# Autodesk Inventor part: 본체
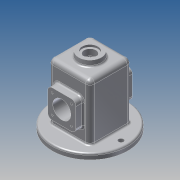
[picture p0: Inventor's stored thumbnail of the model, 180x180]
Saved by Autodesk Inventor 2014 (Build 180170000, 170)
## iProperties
Created: 2021-08
Part Number: 본체
Material: 알루미늄 6061
Document SubType Name: Modeling
Designer: kb542-02
Mass: 821.659 g
Surface Area: 959.349 cm^2
Volume: 303.195 cm^3
Density: 2.71 g/cm^3
Appearance: 알루미늄 - 평지
Author: kb542-02
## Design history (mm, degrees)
sketch "스케치1"
  geometry: L1 (37, 37)-(-37, 37); L2 (-37, 37)-(-37, -37); L3 (-37, -37)-(37, -37); L4 (37, -37)-(37, 37); L5 (37, 37)-(-37, -37); L6 (-37, 37)-(37, -37); 1 further point
  constraints: 12 end point, 2 midpoint, 2 parallel, 1 horizontal, 1 perpendicular
  dimensions: "d0" = 74 distance between parallel lines of L3 L1; "d1" = 74 distance between parallel lines of L4 L2
extrude "돌출1" new body sketch "스케치1" distance "d2" = 110; taper "d3" = 0 deg
sketch "스케치2"
  geometry: L1 (32, 32)-(-32, 32); L2 (-32, 32)-(-32, -32); L3 (-32, -32)-(32, -32); L4 (32, -32)-(32, 32); L5 (32, 32)-(-32, -32); L6 (-32, 32)-(32, -32); 1 further point
  constraints: 12 end point, 2 midpoint, 2 parallel, 1 horizontal, 1 perpendicular
  dimensions: "d4" = 64 distance of L2.end L3.end; "d5" = 64 distance between parallel lines of L3 L1
extrude "돌출2" cut sketch "스케치2" distance "d6" = 105; taper "d7" = 0 deg
sketch "스케치3"
  geometry: L1 (55, 43.476)-(55, -45.763); L2 (0, -32)-(0, 32) reference; L3 (39, 32)-(39, 25); L4 (39, 25)-(32.548, 25); L5 (32.548, 25)-(30, 32); L6 (0, 32)-(105, 32) reference; 1 further point
  constraints: 8 end point, 2 point on line, 1 parallel, 1 perpendicular, 1 vertical
  dimensions: "d8" = 55 distance from line of L2 L1.end; "d11" = 50 diameter of L5.end L1; "d12" = 32 diameter of L3 L1; "d13" = 110 deg angle of L6 L5; "d14" = 7 distance between parallel lines of L6 L4
revolve "회전1" sketch "스케치3" stored, may be unused: angle "d15" = 90 deg
sketch "스케치4"
  geometry: L1 (0, 0)-(0, 110) reference; C1 r 16 at (37, 55); 1 further point
  constraints: 1 centre point
  dimensions: "d16" = 55 distance of point (37, 0) C1.centre; "d17" = 32 diameter of C1; "d18" = 37 distance from line of L1 C1.centre
extrude "돌출3" cut sketch "스케치4" distance "d19" = 105; taper "d20" = 0 deg
sketch "스케치5"
  geometry: L1 (12, 30)-(62, 30); L2 (62, 30)-(62, 80); L3 (62, 80)-(12, 80); L4 (12, 80)-(12, 30); L5 (12, 30)-(62, 80); L6 (62, 30)-(12, 80); C1 r 16 at (37, 55) reference; 1 further point
  constraints: 12 end point, 2 midpoint, 2 parallel, 1 horizontal, 1 perpendicular
  dimensions: "d21" = 50 distance of L2.end L3.end; "d22" = 50 distance between parallel lines of L3 L1
extrude "돌출4" join sketch "스케치5" distance "d23" = 13; taper "d24" = 0 deg
sketch "스케치6"
  geometry: L1 (-37, 37)-(-37, -37) reference; L2 (37, 37)-(-37, 37) reference; L3 (37, -37)-(37, 37) reference; L4 (-37, -37)-(37, -37) reference; C1 r 67 at (0, 0); 1 further point
  constraints: 1 centre point, 1 coincident
  dimensions: "d25" = 134 diameter of C1
extrude "돌출5" join sketch "스케치6" distance "d26" = 10; taper "d27" = 0 deg
sketch "스케치7"
  geometry: L1 (120, 0)-(120, -20); L2 (120, -20)-(105, -21.577); L3 (0, 0)-(146.518, 0); L4 (105, -32)-(105, 32) reference; L5 (105, -21.577)-(137.115, -21.577); L6 (0, -32)-(0, 32) reference; L7 (105, -21.577)-(105, 0); L8 (120, 0)-(105, 0)
  constraints: 12 end point, 2 perpendicular, 2 point on line, 1 collinear, 1 horizontal, 1 midpoint
  dimensions: "d28" = 6 deg angle of L2 L5; "d29" = 40 diameter of L1.end L3; "d30" = 120 distance between parallel lines of L6 L1
revolve "회전2" sketch "스케치7" stored, may be unused: angle "d31" = 90 deg
sketch "스케치8"
  geometry: C1 r 20 at (0, 0) reference; 1 further point
  constraints: 1 coincident
hole "구멍1" sketch "스케치8" at (0, 0) diameter "d32" = 21; stored, may be unused: countersink angle "d36" = 90 deg, drill point angle "d38" = 0 deg; dims "d33" = 6, "d34" = 28, "d35" = 4, "d37" = 8
sketch "스케치9" dims "d39" = 110
  geometry: C1 r 67 at (0, 0) reference; C2 r 4.5 at (-55, 0); 1 further point
  constraints: 2 horizontal alignment, 1 centre point, 1 coincident, 2 other
  dimensions: "d40" = 9 diameter of C2
extrude "돌출6" cut sketch "스케치9" distance "d41" = 10; taper "d42" = 0 deg
sketch "스케치10" dims "d19" = 105, "d20" = 0
  geometry: L1 (20, 38)-(54, 38); L2 (54, 38)-(54, 72); L3 (54, 72)-(20, 72); L4 (20, 72)-(20, 38); L5 (20, 38)-(54, 72); L6 (54, 38)-(20, 72); C1 r 16 at (37, 55) reference; 5 further points
  constraints: 12 end point, 4 coincident, 2 midpoint, 2 parallel, 1 horizontal, 1 perpendicular
  dimensions: "d43" = 34 distance of L2.end L3.end; "d44" = 34 distance between parallel lines of L3 L1
hole "구멍2" sketch "스케치10" at (54, 72), (20, 72), (20, 38), (54, 38) diameter "d45" = 3.242; stored, may be unused: countersink angle "d49" = 90 deg, drill point angle "d51" = 118 deg; dims "d46" = 8, "d47" = 28, "d48" = 4, "d50" = 10
fillet "모깎기1" dims "d52" = 8
fillet "모깎기2" dims "d53" = 8
fillet "모깎기3" dims "d54" = 3
fillet "모깎기4" dims "d55" = 8
fillet "모깎기5" dims "d56" = 3
fillet "모깎기6" dims "d57" = 8
fillet "모깎기7" dims "d58" = 3
fillet "모깎기8" dims "d59" = 3
fillet "모깎기9" dims "d60" = 3
sketch "스케치11"
  geometry: L1 (9, 18)-(49, 18) reference; L2 (-8, 0)-(-8, -89) reference; 2 further points
  constraints: 1 other
  dimensions: "d61" = 28 distance from line of point (29, -10) L1; "d62" = 37 distance from line of L2 point (29, -10)
feature "엠보싱1" sketch "스케치11" dims "d0" = 74, "d1" = 74, "d8" = 55, "d11" = 50, "d12" = 32, "d13" = 110 deg, "d14" = 7, "d63" = 0.5, "d64" = 0
node "솔리드1"
mirror "대칭1"
mirror "대칭2"
mirror "대칭3"
mirror "대칭4"
